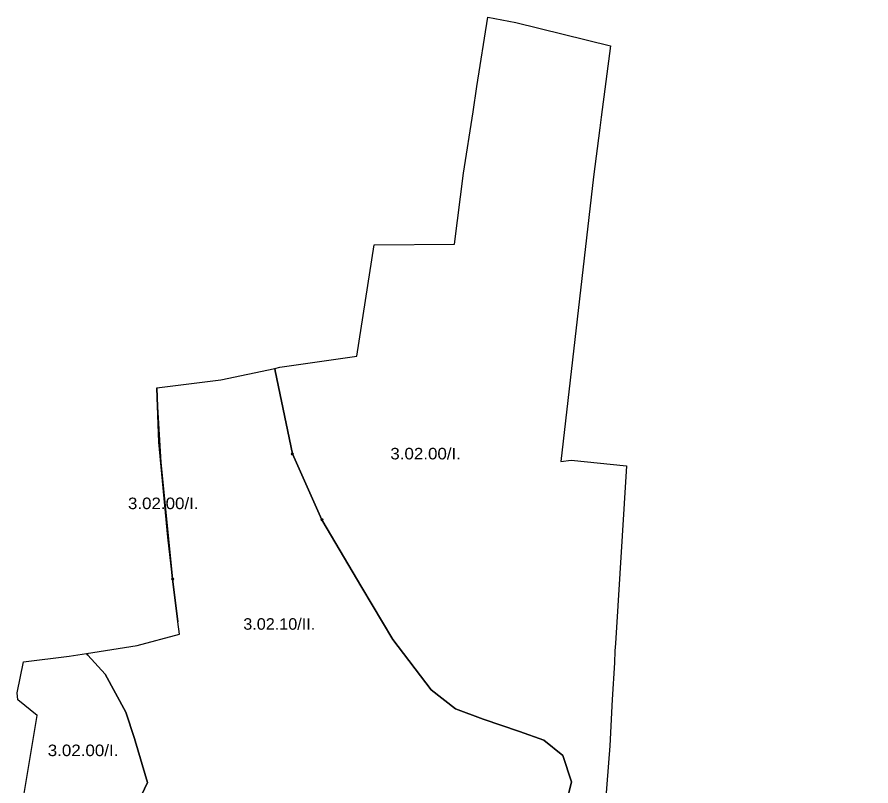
# Model space of a CAD drawing. Extents: x -650455 to -642254, y -1075222 to -1066610.
# Drawn here: x -645891 to -645150, y -1067624 to -1066957 of the extents above; entities that cross this region are included whole.
import ezdxf
from ezdxf.enums import TextEntityAlignment as Align

# ---------------------------------------------------------------- set-up
doc = ezdxf.new("R2010")
doc.units = 0
doc.header["$LTSCALE"] = 4
doc.header["$PDMODE"] = 32
doc.header["$PDSIZE"] = 2
for name, color, linetype, lineweight in [('1', 7, 'Continuous', 25), ('11', 7, 'Continuous', 13), ('12', 7, 'Continuous', 13)]:
    doc.layers.add(name, color=color, linetype=linetype, lineweight=lineweight)
doc.layers.add('2', color=7, linetype='Continuous')

msp = doc.modelspace()

# ---------------------------------------------------------------- linework, layer by layer
at = {"layer": '1'}
for points in [[(-645413.813, -1067638.626), (-645409.312, -1067620.625), (-645416.812, -1067598), (-645433.375, -1067584.501), (-645454.437, -1067577.001), (-645486.062, -1067566.376), (-645510.188, -1067557.375), (-645531.25, -1067540.875), (-645564.375, -1067497.126), (-645591.438, -1067452.001), (-645626.062, -1067393.25), (-645651.688, -1067336.126), (-645666.562, -1067264.001), (-645666.977, -1067261.871), (-645662.58, -1067260.941), (-645595.88, -1067251.4), (-645580.79, -1067154.711), (-645510.95, -1067154.14), (-645503.12, -1067092.52), (-645494.89, -1067039.24), (-645491.53, -1067017.12), (-645482.19, -1066956.971), (-645457.651, -1066961.687), (-645375.661, -1066981.798)], [(-645375.661, -1066981.798), (-645383.686, -1067043.814), (-645384.878, -1067053.018), (-645390.401, -1067095.701), (-645418.542, -1067342.638), (-645409.605, -1067341.495), (-645361.617, -1067346.492), (-645371.183, -1067500.595), (-645371.73, -1067507.06), (-645372.231, -1067517.464), (-645374.197, -1067549.139), (-645376.168, -1067589.471), (-645383.93, -1067689.29), (-645382.349, -1067689.308), (-645382.611, -1067693.192), (-645323.149, -1067700.972), (-645196.557, -1067721.558), (-645192.4, -1067722.74), (-645185.42, -1067724.72), (-645152.82, -1067730.251), (-645149.527, -1067730.871), (-645149.54, -1067732.723)], [(-645790.813, -1067649.501), (-645777.5, -1067621.251), (-645788.25, -1067585.125), (-645788.254, -1067585.104), (-645788.625, -1067583), (-645796.188, -1067560.375), (-645814.25, -1067527.251), (-645829.312, -1067510.75), (-645830.352, -1067509.283), (-645786.52, -1067502.401), (-645749.67, -1067492.54), (-645751.066, -1067481.89), (-645755.688, -1067444.626), (-645765.937, -1067343.5), (-645768.75, -1067295.25), (-645769.307, -1067278.67), (-645713.88, -1067271.801), (-645666.977, -1067261.871), (-645666.562, -1067264.001), (-645651.688, -1067336.126), (-645626.062, -1067393.25), (-645591.438, -1067452.001), (-645564.375, -1067497.126), (-645531.25, -1067540.875), (-645510.188, -1067557.375), (-645486.062, -1067566.376), (-645454.437, -1067577.001), (-645433.375, -1067584.501), (-645416.812, -1067598)], [(-645416.812, -1067598), (-645409.312, -1067620.625), (-645413.813, -1067638.626), (-645421.375, -1067644.751), (-645436.375, -1067646.251), (-645466.563, -1067650.126)]]:
    msp.add_lwpolyline(points, dxfattribs=at)
for points in [[(-645751.066, -1067481.89), (-645754.45, -1067456.07), (-645759.82, -1067408.401), (-645767.6, -1067326.001), (-645769.39, -1067278.681), (-645769.307, -1067278.67), (-645768.75, -1067295.25), (-645765.937, -1067343.5), (-645755.688, -1067444.626)], [(-645802.687, -1067663.876), (-645809.375, -1067672.25), (-645814.125, -1067677.751), (-645816.835, -1067678.312), (-645839.087, -1067682.923), (-645837.619, -1067663.994), (-645836.027, -1067656.984), (-645867.933, -1067653.635), (-645883.859, -1067650.419), (-645884.5, -1067630.76), (-645873.323, -1067563.051), (-645890.073, -1067549.417), (-645890.669, -1067543.411), (-645885.177, -1067516.651), (-645845.49, -1067511.661), (-645830.352, -1067509.283), (-645829.312, -1067510.75), (-645814.25, -1067527.251), (-645796.188, -1067560.375), (-645788.625, -1067583), (-645788.254, -1067585.104), (-645788.25, -1067585.125), (-645777.5, -1067621.251), (-645790.813, -1067649.501)]]:
    msp.add_lwpolyline(points, close=True, dxfattribs=at)
at = {"layer": '11'}
msp.add_line((-645651.688, -1067336.126), (-645626.062, -1067393.25), dxfattribs=at)
for points in [[(-645371.73, -1067507.06), (-645371.183, -1067500.595), (-645361.617, -1067346.492), (-645409.605, -1067341.495), (-645418.542, -1067342.638), (-645390.401, -1067095.701), (-645384.878, -1067053.018), (-645383.686, -1067043.814), (-645375.661, -1066981.798), (-645457.651, -1066961.687), (-645482.19, -1066956.971), (-645491.53, -1067017.12), (-645494.89, -1067039.24), (-645503.12, -1067092.52), (-645510.95, -1067154.14), (-645580.79, -1067154.711), (-645595.88, -1067251.4), (-645662.58, -1067260.941), (-645666.977, -1067261.871), (-645666.562, -1067264.001), (-645651.688, -1067336.126)], [(-645626.062, -1067393.25), (-645591.438, -1067452.001), (-645564.375, -1067497.126), (-645531.25, -1067540.875), (-645510.188, -1067557.375), (-645486.062, -1067566.376), (-645454.437, -1067577.001), (-645433.375, -1067584.501), (-645416.812, -1067598), (-645409.312, -1067620.625), (-645413.813, -1067638.626)], [(-645383.93, -1067689.29), (-645376.168, -1067589.471), (-645374.197, -1067549.139), (-645372.231, -1067517.464), (-645371.73, -1067507.06)]]:
    msp.add_lwpolyline(points, dxfattribs=at)
msp.add_lwpolyline([(-645884.5, -1067630.76), (-645883.859, -1067650.419), (-645867.933, -1067653.635), (-645836.027, -1067656.984), (-645837.619, -1067663.994), (-645839.087, -1067682.923), (-645816.835, -1067678.312), (-645814.125, -1067677.751), (-645809.375, -1067672.25), (-645802.687, -1067663.876), (-645790.813, -1067649.501), (-645777.5, -1067621.251), (-645788.25, -1067585.125), (-645788.254, -1067585.104), (-645788.625, -1067583), (-645796.188, -1067560.375), (-645814.25, -1067527.251), (-645829.312, -1067510.75), (-645830.352, -1067509.283), (-645845.49, -1067511.661), (-645885.177, -1067516.651), (-645890.669, -1067543.411), (-645890.073, -1067549.417), (-645873.323, -1067563.051)], close=True, dxfattribs=at)
for p in [(-645651.688, -1067336.126), (-645626.062, -1067393.25)]:
    msp.add_point(p, dxfattribs=at)
at = {"layer": '12'}
for points in [[(-645413.813, -1067638.626), (-645409.312, -1067620.625), (-645416.812, -1067598), (-645433.375, -1067584.501), (-645454.437, -1067577.001), (-645486.062, -1067566.376), (-645510.188, -1067557.375), (-645531.25, -1067540.875), (-645564.375, -1067497.126), (-645591.438, -1067452.001), (-645626.062, -1067393.25), (-645651.688, -1067336.126), (-645666.562, -1067264.001), (-645666.977, -1067261.871), (-645713.88, -1067271.801), (-645769.307, -1067278.67), (-645768.75, -1067295.25), (-645765.937, -1067343.5), (-645755.688, -1067444.626)], [(-645755.688, -1067444.626), (-645751.066, -1067481.89), (-645749.67, -1067492.54), (-645786.52, -1067502.401), (-645830.352, -1067509.283), (-645829.312, -1067510.75), (-645814.25, -1067527.251), (-645796.188, -1067560.375), (-645788.625, -1067583), (-645788.254, -1067585.104), (-645788.25, -1067585.125), (-645777.5, -1067621.251), (-645790.813, -1067649.501), (-645802.687, -1067663.876), (-645796.062, -1067664.75), (-645790.875, -1067664.75), (-645710.625, -1067646.5)]]:
    msp.add_lwpolyline(points, dxfattribs=at)
msp.add_point((-645755.688, -1067444.626), dxfattribs=at)

# ---------------------------------------------------------------- texts
at = {"layer": '2'}
for s, width, p in [('3.02.00/I.', 1.1, (-645536.022, -1067340.863)), ('3.02.00/I.', 1.1, (-645763.764, -1067384.029)), ('3.02.10/II.', 1.05, (-645663.094, -1067488.705)), ('3.02.00/I.', 1.1, (-645833.378, -1067598.402))]:
    msp.add_text(s, height=10, dxfattribs=dict(at, width=width)).set_placement(p, align=Align.CENTER)

doc.saveas('drawing.dxf')
